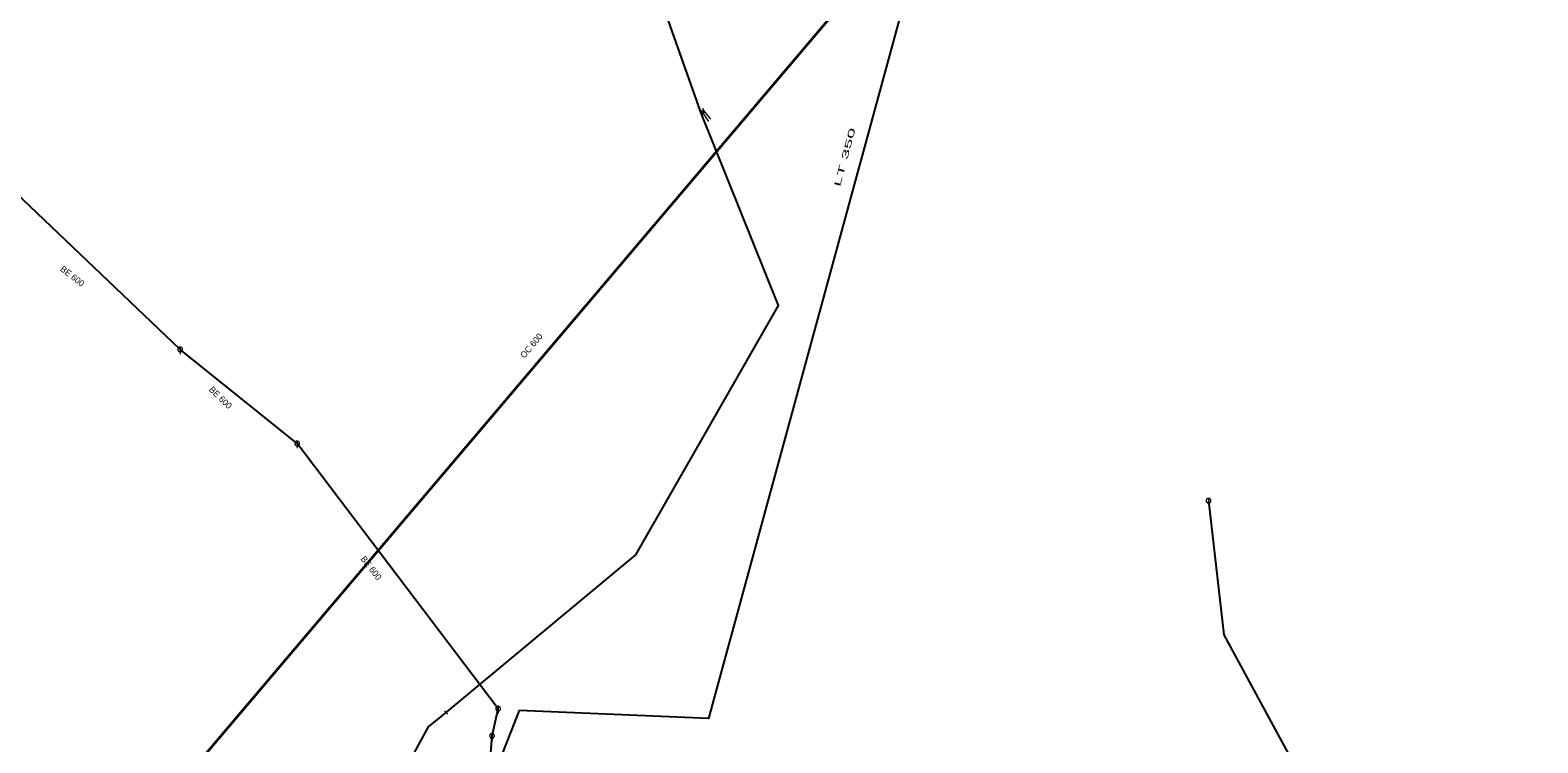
# Model space of a CAD drawing. Extents: x -687468 to -685917, y -974192 to -973456.
# Drawn here: x -686248.8 to -686089.3, y -973947 to -973871.6 of the extents above; entities that cross this region are included whole.
import ezdxf
from ezdxf.enums import TextEntityAlignment as Align

# ---------------------------------------------------------------- set-up
doc = ezdxf.new("R2010")
doc.units = 0
doc.header["$LTSCALE"] = 0.27
for name, color, linetype, lineweight in [('1', 7, 'Continuous', 13), ('13', 7, 'Continuous', 13), ('14', 7, 'Continuous', 25), ('17', 7, 'Continuous', 25), ('22', 7, 'Continuous', 13), ('34', 7, 'Continuous', 13)]:
    doc.layers.add(name, color=color, linetype=linetype, lineweight=lineweight)

msp = doc.modelspace()

# ---------------------------------------------------------------- linework, layer by layer
at = {"layer": '13'}
for p, q in [((-686177.649, -973880.329), (-686177.02, -973881.28)), ((-686177.539, -973880.129), (-686176.82, -973881.05))]:
    msp.add_line(p, q, dxfattribs=at)
at = {"layer": '14', "lineweight": 13}
for p, q in [((-686177.867, -973880.202), (-686177.539, -973880.129)), ((-686177.797, -973880.398), (-686177.649, -973880.329))]:
    msp.add_line(p, q, dxfattribs=at)
at = {"layer": '14'}
for p, q in [((-686232.891, -973905.396), (-686251.059, -973888.086)), ((-686220.517, -973915.338), (-686232.891, -973905.396)), ((-686199.273, -973943.377), (-686220.517, -973915.338))]:
    msp.add_line(p, q, dxfattribs=at)
for points in [[(-686124.153, -973921.386), (-686122.535, -973935.572), (-686106.927, -973964.355)], [(-686187.015, -973949.094), (-686200.653, -973955.607), (-686199.917, -973946.239), (-686199.273, -973943.377)]]:
    msp.add_lwpolyline(points, dxfattribs=at)
at = {"layer": '17', "lineweight": 35}
msp.add_lwpolyline([(-686160.425, -973551.891), (-686169.469, -973574.282), (-686122.999, -973646.384), (-686098.932, -973712.353), (-686089.329, -973782.048), (-686297.791, -974027.806), (-686326.807, -974076.614), (-686379.703, -974100.561), (-686411.584, -974111.413)], dxfattribs=at)
at = {"layer": '17'}
for points in [[(-686144.92, -973826.734), (-686177.013, -973944.41), (-686197.048, -973943.572), (-686232.018, -974032.331), (-686151.042, -974110.8), (-686189.024, -974153.642), (-686204.782, -974140.962), (-686246.709, -974191.881)], [(-686204.755, -973943.783), (-686184.694, -973927.101), (-686169.64, -973900.75), (-686177.797, -973880.398), (-686177.867, -973880.202), (-686193.325, -973836.589)], [(-686150.349, -974110.866), (-686211.068, -974050.449), (-686245.909, -974017.381), (-686206.618, -973945.282), (-686204.755, -973943.783)]]:
    msp.add_lwpolyline(points, dxfattribs=at)
at = {"layer": '22'}
for p, q in [((-686232.89, -973905.144), (-686232.891, -973905.887)), ((-686220.516, -973915.086), (-686220.517, -973915.83)), ((-686124.152, -973921.135), (-686124.153, -973921.879)), ((-686199.272, -973943.125), (-686199.273, -973943.869)), ((-686199.916, -973945.987), (-686199.917, -973946.73))]:
    msp.add_line(p, q, dxfattribs=at)
for points in [[(-686232.639, -973905.396), (-686232.64, -973905.37), (-686232.644, -973905.344), (-686232.65, -973905.318), (-686232.66, -973905.294), (-686232.672, -973905.27), (-686232.686, -973905.248), (-686232.703, -973905.227), (-686232.721, -973905.209), (-686232.742, -973905.192), (-686232.764, -973905.178), (-686232.788, -973905.166), (-686232.812, -973905.156), (-686232.838, -973905.15), (-686232.864, -973905.146), (-686232.89, -973905.144), (-686232.916, -973905.145), (-686232.942, -973905.149), (-686232.968, -973905.155), (-686232.993, -973905.165), (-686233.016, -973905.177), (-686233.038, -973905.191), (-686233.059, -973905.208), (-686233.077, -973905.226), (-686233.094, -973905.247), (-686233.108, -973905.269), (-686233.12, -973905.293), (-686233.13, -973905.317), (-686233.137, -973905.343), (-686233.141, -973905.369), (-686233.142, -973905.395), (-686233.142, -973905.421), (-686233.138, -973905.447), (-686233.131, -973905.473), (-686233.121, -973905.498), (-686233.109, -973905.521), (-686233.095, -973905.543), (-686233.078, -973905.564), (-686233.06, -973905.582), (-686233.039, -973905.599), (-686233.017, -973905.613), (-686232.994, -973905.625), (-686232.969, -973905.635), (-686232.943, -973905.642), (-686232.917, -973905.646), (-686232.891, -973905.647), (-686232.865, -973905.647), (-686232.839, -973905.643), (-686232.813, -973905.636), (-686232.789, -973905.626), (-686232.765, -973905.614), (-686232.743, -973905.6), (-686232.722, -973905.583), (-686232.704, -973905.565), (-686232.687, -973905.544), (-686232.673, -973905.522), (-686232.661, -973905.499), (-686232.651, -973905.474), (-686232.645, -973905.448), (-686232.641, -973905.422)], [(-686220.265, -973915.338), (-686220.266, -973915.312), (-686220.27, -973915.286), (-686220.276, -973915.26), (-686220.286, -973915.236), (-686220.298, -973915.212), (-686220.312, -973915.19), (-686220.329, -973915.169), (-686220.347, -973915.151), (-686220.368, -973915.134), (-686220.39, -973915.12), (-686220.414, -973915.108), (-686220.438, -973915.098), (-686220.464, -973915.092), (-686220.49, -973915.088), (-686220.516, -973915.086), (-686220.542, -973915.087), (-686220.568, -973915.091), (-686220.594, -973915.097), (-686220.619, -973915.107), (-686220.642, -973915.119), (-686220.664, -973915.133), (-686220.685, -973915.15), (-686220.703, -973915.168), (-686220.72, -973915.189), (-686220.734, -973915.211), (-686220.746, -973915.235), (-686220.756, -973915.259), (-686220.763, -973915.285), (-686220.767, -973915.311), (-686220.769, -973915.337), (-686220.768, -973915.363), (-686220.764, -973915.389), (-686220.757, -973915.415), (-686220.747, -973915.44), (-686220.735, -973915.463), (-686220.721, -973915.485), (-686220.704, -973915.506), (-686220.686, -973915.524), (-686220.665, -973915.541), (-686220.643, -973915.555), (-686220.62, -973915.567), (-686220.595, -973915.577), (-686220.569, -973915.584), (-686220.543, -973915.588), (-686220.517, -973915.59), (-686220.491, -973915.589), (-686220.465, -973915.585), (-686220.439, -973915.578), (-686220.415, -973915.568), (-686220.391, -973915.556), (-686220.369, -973915.542), (-686220.348, -973915.525), (-686220.33, -973915.507), (-686220.313, -973915.486), (-686220.299, -973915.464), (-686220.287, -973915.441), (-686220.277, -973915.416), (-686220.271, -973915.39), (-686220.267, -973915.364)], [(-686123.901, -973921.387), (-686123.902, -973921.361), (-686123.906, -973921.335), (-686123.912, -973921.309), (-686123.922, -973921.285), (-686123.934, -973921.261), (-686123.948, -973921.239), (-686123.965, -973921.218), (-686123.983, -973921.2), (-686124.004, -973921.183), (-686124.026, -973921.169), (-686124.05, -973921.157), (-686124.074, -973921.147), (-686124.1, -973921.141), (-686124.126, -973921.137), (-686124.152, -973921.135), (-686124.178, -973921.136), (-686124.204, -973921.14), (-686124.23, -973921.146), (-686124.255, -973921.156), (-686124.278, -973921.168), (-686124.3, -973921.182), (-686124.321, -973921.199), (-686124.339, -973921.217), (-686124.356, -973921.238), (-686124.37, -973921.26), (-686124.382, -973921.284), (-686124.392, -973921.308), (-686124.399, -973921.334), (-686124.403, -973921.36), (-686124.405, -973921.386), (-686124.404, -973921.412), (-686124.4, -973921.438), (-686124.393, -973921.464), (-686124.383, -973921.489), (-686124.371, -973921.512), (-686124.357, -973921.534), (-686124.34, -973921.555), (-686124.322, -973921.573), (-686124.301, -973921.59), (-686124.279, -973921.604), (-686124.256, -973921.616), (-686124.231, -973921.626), (-686124.205, -973921.633), (-686124.179, -973921.637), (-686124.153, -973921.639), (-686124.127, -973921.638), (-686124.101, -973921.634), (-686124.075, -973921.627), (-686124.051, -973921.617), (-686124.027, -973921.605), (-686124.005, -973921.591), (-686123.984, -973921.574), (-686123.966, -973921.556), (-686123.949, -973921.535), (-686123.935, -973921.513), (-686123.923, -973921.49), (-686123.913, -973921.465), (-686123.907, -973921.439), (-686123.903, -973921.413)], [(-686199.021, -973943.377), (-686199.022, -973943.351), (-686199.026, -973943.325), (-686199.032, -973943.299), (-686199.042, -973943.275), (-686199.054, -973943.251), (-686199.068, -973943.229), (-686199.085, -973943.208), (-686199.103, -973943.19), (-686199.124, -973943.173), (-686199.146, -973943.159), (-686199.17, -973943.147), (-686199.194, -973943.137), (-686199.22, -973943.131), (-686199.246, -973943.127), (-686199.272, -973943.125), (-686199.298, -973943.126), (-686199.324, -973943.13), (-686199.35, -973943.136), (-686199.375, -973943.146), (-686199.398, -973943.158), (-686199.42, -973943.172), (-686199.441, -973943.189), (-686199.459, -973943.207), (-686199.476, -973943.228), (-686199.49, -973943.25), (-686199.502, -973943.274), (-686199.512, -973943.298), (-686199.519, -973943.324), (-686199.523, -973943.35), (-686199.525, -973943.376), (-686199.524, -973943.402), (-686199.52, -973943.428), (-686199.513, -973943.454), (-686199.503, -973943.479), (-686199.491, -973943.502), (-686199.477, -973943.524), (-686199.46, -973943.545), (-686199.442, -973943.563), (-686199.421, -973943.58), (-686199.399, -973943.594), (-686199.376, -973943.606), (-686199.351, -973943.616), (-686199.325, -973943.623), (-686199.299, -973943.627), (-686199.273, -973943.629), (-686199.247, -973943.628), (-686199.221, -973943.624), (-686199.195, -973943.617), (-686199.171, -973943.607), (-686199.147, -973943.595), (-686199.125, -973943.581), (-686199.104, -973943.564), (-686199.086, -973943.546), (-686199.069, -973943.525), (-686199.055, -973943.503), (-686199.043, -973943.48), (-686199.033, -973943.455), (-686199.027, -973943.429), (-686199.023, -973943.403)], [(-686199.665, -973946.239), (-686199.666, -973946.213), (-686199.67, -973946.187), (-686199.676, -973946.161), (-686199.686, -973946.137), (-686199.698, -973946.113), (-686199.712, -973946.091), (-686199.729, -973946.07), (-686199.747, -973946.052), (-686199.768, -973946.035), (-686199.79, -973946.021), (-686199.814, -973946.009), (-686199.838, -973945.999), (-686199.864, -973945.993), (-686199.89, -973945.989), (-686199.916, -973945.987), (-686199.942, -973945.988), (-686199.968, -973945.992), (-686199.994, -973945.998), (-686200.019, -973946.008), (-686200.042, -973946.02), (-686200.064, -973946.034), (-686200.085, -973946.051), (-686200.103, -973946.069), (-686200.12, -973946.09), (-686200.134, -973946.112), (-686200.146, -973946.136), (-686200.156, -973946.16), (-686200.163, -973946.186), (-686200.167, -973946.212), (-686200.169, -973946.238), (-686200.168, -973946.264), (-686200.164, -973946.29), (-686200.157, -973946.316), (-686200.147, -973946.341), (-686200.135, -973946.364), (-686200.121, -973946.386), (-686200.104, -973946.407), (-686200.086, -973946.425), (-686200.065, -973946.442), (-686200.043, -973946.456), (-686200.02, -973946.468), (-686199.995, -973946.478), (-686199.969, -973946.485), (-686199.943, -973946.489), (-686199.917, -973946.49), (-686199.891, -973946.49), (-686199.865, -973946.486), (-686199.839, -973946.479), (-686199.815, -973946.469), (-686199.791, -973946.457), (-686199.769, -973946.443), (-686199.748, -973946.426), (-686199.73, -973946.408), (-686199.713, -973946.387), (-686199.699, -973946.365), (-686199.687, -973946.342), (-686199.677, -973946.317), (-686199.671, -973946.291), (-686199.667, -973946.265)]]:
    msp.add_lwpolyline(points, close=True, dxfattribs=at)
at = {"layer": '34'}
for p, q in [((-686177.485, -973880.371), (-686177.592, -973879.886)), ((-686177.544, -973880.554), (-686177.753, -973880.103)), ((-686204.583, -973943.962), (-686204.926, -973943.603))]:
    msp.add_line(p, q, dxfattribs=at)

# ---------------------------------------------------------------- texts
at = {"layer": '1', "width": 2.3}
msp.add_text('LT 350', height=0.6667, rotation=75, dxfattribs=at).set_placement((-686162.297, -973885.155), align=Align.CENTER)
at = {"layer": '1'}
for s, rotation, p in [('BE 600', 322, (-686244.497, -973897.908)), ('OC 600', 50, (-686195.498, -973905.211)), ('BE 600', 316, (-686228.864, -973910.723)), ('BE 600', 308, (-686212.959, -973928.704))]:
    msp.add_text(s, height=0.6667, rotation=rotation, dxfattribs=at).set_placement(p, align=Align.CENTER)

doc.saveas('drawing.dxf')
